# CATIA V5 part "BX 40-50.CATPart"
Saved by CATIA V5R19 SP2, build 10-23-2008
Part number: BX 40-50
Bounding box of the stored display mesh (mm): x -12.497 to 12.497, y -12.358 to 12.358, z 0 to 195
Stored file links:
  C:\Users\Bora\Desktop\3D Katı model\BX serisi\BX 40\BX 40-10\BX 40-50.CATPart
  C:\Program Files\Dassault Systemes\B19\intel_a\reffiles\standard\MetricThickPitch.txt
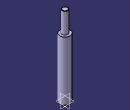
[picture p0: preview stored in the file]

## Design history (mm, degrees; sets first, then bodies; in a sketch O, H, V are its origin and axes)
Body1 (main body)
  Sketch1 on yz-plane, origin (0, 0, 0), H (0, 1, 0), V (0, 0, 1)
    point P3 (7, 194)
    point P5 (7, 194)
    line L1 (12.5, 144) -> (12.5, 0)
    line L2 (7, 194) -> (7, 144)
    arc A1 centre (6, 194) radius 1 from (7, 194) to (6, 195) ccw
    line L3 (6, 195) -> (0, 195)
    point P7 (0, 195)
    line L4 (7, 144) -> (12.5, 144)
    line L5 (12.5, 0) -> (0, 0)
    tangency: L3 A1
    coincidence: P7 V, P3 P5
    horizontal: L4 H, L5 H
  Shaft1: profile Sketch1, axis Sketch1.V, angle 360
  Sketch2 on face of Shaft1 from Sketch1.L5, origin (0, 0, 0), H (1, 0, 0), V (0, -1, 0)
    point P1 (6, 0)
    distance P1 V = 6
  Hole1: placed by Sketch2, at (6, 0, 0) direction (0, 0, 1), diameter 3.242, depth 5, threaded "M4", thread diameter 4, thread depth 5, pitch 0.7
  Sketch3 on face of Shaft1 from Sketch1.L5, origin (0, 0, 0), H (1, 0, 0), V (0, -1, 0)
    point P1 (-6, 0)
    distance P1 V = 6
    distance P1 H = 0
  Hole2: placed by Sketch3, at (-6, 0, 0) direction (0, 0, 1), diameter 3.242, depth 5, threaded "M4", thread diameter 4, thread depth 5, pitch 0.7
